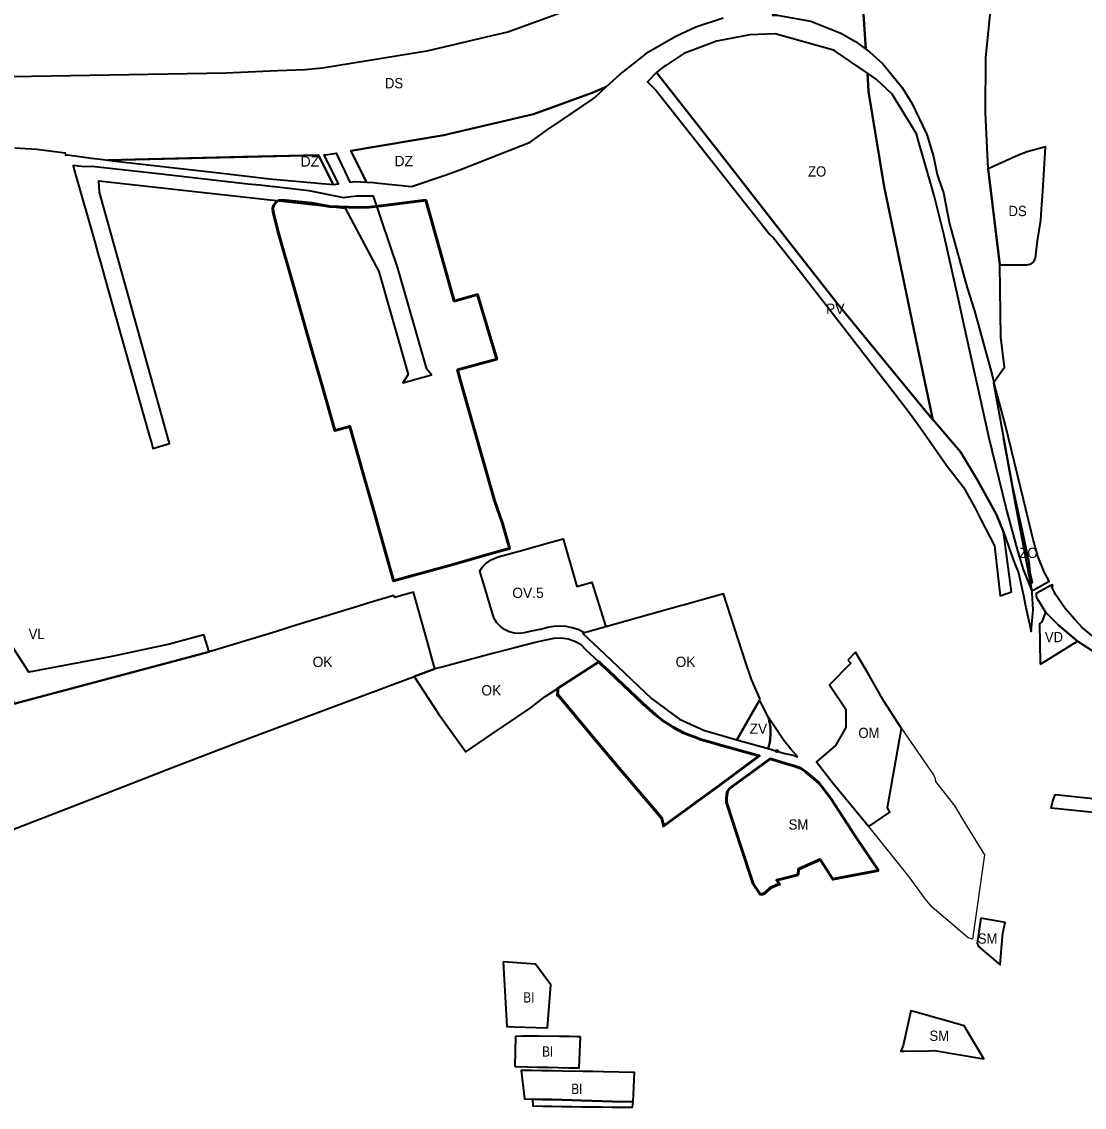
# Model space of a CAD drawing. Extents: x -650276 to -642489, y -1074311 to -1066658.
# Drawn here: x -649019 to -647782, y -1070372 to -1069108 of the extents above; entities that cross this region are included whole.
import ezdxf

# ---------------------------------------------------------------- set-up
doc = ezdxf.new("R2010")
doc.units = 0
doc.header["$LTSCALE"] = 4.8
doc.header["$PDMODE"] = 32
doc.header["$PDSIZE"] = 2.4
for name, color, linetype, lineweight in [('11', 7, 'Continuous', 35), ('12', 7, 'Continuous', 35), ('13', 7, 'Continuous', 35), ('15', 7, 'Continuous', 35), ('18', 7, 'Continuous', 35), ('2', 7, 'Continuous', 35), ('24', 7, 'Continuous', 35), ('25', 7, 'Continuous', 35), ('35', 7, 'Continuous', 35), ('40', 7, 'Continuous', 35), ('42', 7, 'Continuous', 35), ('60', 7, 'Continuous', 53), ('61', 7, 'Continuous', 25)]:
    doc.layers.add(name, color=color, linetype=linetype, lineweight=lineweight)
doc.layers.add('62', color=7, linetype='Continuous')

msp = doc.modelspace()

# ---------------------------------------------------------------- linework, layer by layer
at = {"layer": '11'}
msp.add_lwpolyline([(-648339.05, -1069812.45), (-648363.68, -1069819.31), (-648371.21, -1069815.56), (-648378.1, -1069813.29), (-648385.21, -1069811.91), (-648392.45, -1069811.44), (-648399.68, -1069811.88), (-648406.84, -1069813.23), (-648414.657, -1069815.246), (-648415.99, -1069815.59), (-648430.881, -1069818.663), (-648433.97, -1069819.3), (-648439.89, -1069819.97), (-648445.8, -1069819.51), (-648451.53, -1069817.98), (-648456.88, -1069815.39), (-648461.64, -1069811.86), (-648465.67, -1069807.49), (-648468.82, -1069802.44), (-648470.97, -1069796.9), (-648480.267, -1069765.316), (-648485.44, -1069747.39), (-648485.14, -1069746.55), (-648483.274, -1069743.777), (-648481.79, -1069741.57), (-648477.39, -1069737.44), (-648476.022, -1069736.525), (-648472.4, -1069734.1), (-648464.45, -1069730.89), (-648439.8, -1069724.19), (-648401.288, -1069713.154), (-648388.631, -1069709.738), (-648372.639, -1069765.241), (-648355.015, -1069760.287)], close=True, dxfattribs=at)
at = {"layer": '12'}
msp.add_lwpolyline([(-648057.11, -1069851.12), (-648053.61, -1069854.64), (-648078.54, -1069880.01), (-648059.32, -1069908.27), (-648059.5, -1069929.52), (-648071.58, -1069950.39), (-648093.67, -1069969.42), (-648074.96, -1069993.46), (-648032.85, -1070044.73), (-648008.18, -1070028.25), (-648010.44, -1070023.66), (-648010.94, -1070022.65), (-647994.71, -1069930.53), (-648015.11, -1069898.98), (-648032.94, -1069867.46), (-648048.08, -1069841.95)], close=True, dxfattribs=at)
at = {"layer": '13'}
msp.add_lwpolyline([(-649048.918, -1070055.852), (-648931.057, -1070010.171), (-648849.532, -1069978.559), (-648767.83, -1069946.87), (-648562.242, -1069870.301), (-648537.86, -1069861.22), (-648541.06, -1069849.78), (-648546.97, -1069828.68), (-648562.87, -1069771.85), (-648579.63, -1069776.66), (-648584.65, -1069778.1), (-648586.09, -1069775.75), (-648593.59, -1069778.06), (-648615.88, -1069784.93), (-648627.99, -1069788.67), (-648665.05, -1069799.99), (-648698.31, -1069810.16), (-648722.24, -1069817.54), (-648772.48, -1069832.83), (-648800.85, -1069841.52), (-649028.017, -1069902.109)], dxfattribs=at)
for points in [[(-648159.1, -1069896.39), (-648169.15, -1069873.81), (-648176.78, -1069851.74), (-648201.83, -1069773.86), (-648247.27, -1069786.64), (-648251.94, -1069787.95), (-648339.05, -1069812.45), (-648363.68, -1069819.31), (-648365.81, -1069819.9), (-648340.38, -1069843.78), (-648285.62, -1069895.71), (-648253.13, -1069919.7), (-648223.99, -1069932.96), (-648218.245, -1069934.595), (-648186.268, -1069943.697), (-648160.04, -1069897.73)], [(-648470.79, -1069843.51), (-648528.11, -1069858.73), (-648537.86, -1069861.22), (-648562.242, -1069870.301), (-648533.79, -1069913.49), (-648502.048, -1069957.969), (-648472.6, -1069937.81), (-648426.82, -1069906.88), (-648409.44, -1069893.25), (-648396.87, -1069885.43), (-648395.03, -1069884.22), (-648347.06, -1069853), (-648361.3, -1069839.7), (-648367.64, -1069833.35), (-648374.89, -1069829.22), (-648382.8, -1069826.55), (-648391.08, -1069825.45), (-648399.4, -1069825.97), (-648412.74, -1069828.72), (-648422.75, -1069830.78), (-648422.75, -1069830.78), (-648447.98, -1069837.44)]]:
    msp.add_lwpolyline(points, close=True, dxfattribs=at)
at = {"layer": '15'}
for points in [[(-648147.81, -1069355.26), (-648143.81, -1069359.39), (-648116.93, -1069393.25), (-648052.62, -1069476.32), (-647995.61, -1069549.95), (-647984.36, -1069564.49), (-647980.21, -1069569.97), (-647974.74, -1069577.39), (-647962.93, -1069594.39), (-647942.48, -1069623.82), (-647922.32, -1069649.56), (-647909.25, -1069673.35), (-647902.18, -1069687.23), (-647886.43, -1069718.16), (-647879.96, -1069776.1), (-647866.4, -1069771.43), (-647866.4, -1069771.43), (-647875.82, -1069701.85), (-647883.51, -1069682.71), (-647885.665, -1069678.788), (-647906.16, -1069641.48), (-647925.99, -1069608.57), (-647967.53, -1069559.94), (-648068.71, -1069436.57), (-648127.77, -1069361.38), (-648203.01, -1069264.73), (-648280.1, -1069166.97), (-648290.39, -1069177.69), (-648280.46, -1069187.61), (-648147.81, -1069355.26)], [(-648642.241, -1069324.949), (-648603.386, -1069398.357), (-648569.22, -1069518.4), (-648575.15, -1069528.35), (-648541.88, -1069518.95), (-648547.3, -1069512.136), (-648581.051, -1069394.771), (-648609.304, -1069310.668), (-648629.16, -1069310.91), (-648641.98, -1069312.45), (-648643.83, -1069312.66), (-648684.39, -1069304.67), (-648724.82, -1069299.92), (-648725.82, -1069299.81), (-648741.58, -1069298.16), (-648755.56, -1069296.7), (-648856.68, -1069285.01), (-648937.2, -1069276.37), (-648945.96, -1069276.64), (-648959.11, -1069275.13), (-648957.74, -1069280), (-648934.38, -1069362.79), (-648929.16, -1069381.32), (-648927.37, -1069387.62), (-648927.38, -1069387.623), (-648918.65, -1069418.53), (-648893.86, -1069506.89), (-648870.76, -1069589.26), (-648867.62, -1069599.37), (-648866.17, -1069604.48), (-648847.097, -1069598.995), (-648928.347, -1069306.125), (-648929.112, -1069293.123)], [(-647815.788, -1070007.72), (-647767.622, -1070012.66), (-647714.989, -1069977.087), (-647654.577, -1069936.255), (-647645.274, -1069949.279), (-647755.356, -1070023.682), (-647763.476, -1070029.17), (-647820.515, -1070023.319), (-647818.81, -1070016.41)], [(-648307.13, -1070365.57), (-648319.33, -1070365.32), (-648331.32, -1070364.96), (-648343.31, -1070364.61), (-648355.27, -1070364.25), (-648367.26, -1070363.9), (-648378.49, -1070363.57), (-648389.95, -1070363.23), (-648401.36, -1070362.89), (-648412.88, -1070362.55), (-648424.31, -1070362.21), (-648424.05, -1070370), (-648412.75, -1070370.28), (-648401.35, -1070370.5), (-648390.06, -1070370.72), (-648378.73, -1070370.94), (-648367.67, -1070371.16), (-648355.67, -1070371.28), (-648343.67, -1070371.41), (-648331.67, -1070371.53), (-648319.67, -1070371.65), (-648307.67, -1070371.78)]]:
    msp.add_lwpolyline(points, close=True, dxfattribs=at)
for points in [[(-649032.928, -1069882.782), (-649028.017, -1069902.109), (-648800.85, -1069841.52), (-648806.946, -1069821.79), (-648846.939, -1069832.584), (-648846.94, -1069832.584)], [(-648846.94, -1069832.584), (-648916.03, -1069847.12), (-649010.55, -1069865.09), (-649029.61, -1069835.47)], [(-648149.67, -1069917.83), (-648147, -1069929), (-648147, -1069938), (-648148, -1069947), (-648150, -1069954), (-648139.78, -1069956.93)], [(-648115.23, -1069963.75), (-648123.45, -1069954.79), (-648131.5, -1069944.75), (-648149.67, -1069917.83)], [(-648139.78, -1069956.93), (-648130.36, -1069959.62), (-648120.68, -1069961.63), (-648115.23, -1069963.75)]]:
    msp.add_lwpolyline(points, dxfattribs=at)
msp.add_point((-648139.78, -1069956.93), dxfattribs=at)
at = {"layer": '18'}
for points in [[(-648182.01, -1070067.11), (-648197.23, -1070020.37), (-648198.22, -1070016.4), (-648198.48, -1070012.3), (-648198.17, -1070008.05), (-648197.19, -1070003.94), (-648194.84, -1070000.49), (-648147.46, -1069966.19)], [(-648147.46, -1069966.19), (-648140.96, -1069968.01), (-648128.48, -1069971.7)], [(-648128.48, -1069971.7), (-648118.75, -1069974.53), (-648111.44, -1069977.32)], [(-648111.44, -1069977.32), (-648105.79, -1069981.56), (-648091.06, -1069994.07), (-648077.68, -1070011.06), (-648046.83, -1070058.62), (-648021.35, -1070096.14), (-648074.76, -1070106.17)], [(-648152.35, -1070121.05), (-648153.85, -1070122.38), (-648156.07, -1070123.54), (-648159.02, -1070123.71), (-648159.89, -1070122.49), (-648167.48, -1070111.75), (-648182.01, -1070067.11)], [(-648074.76, -1070106.17), (-648089.22, -1070083.27), (-648114.7, -1070094.68), (-648115.11, -1070101.26), (-648139.91, -1070107.48), (-648136.61, -1070111.97)], [(-648136.61, -1070111.97), (-648139.45, -1070112.79), (-648147.02, -1070116.35), (-648152.35, -1070121.05)]]:
    msp.add_lwpolyline(points, dxfattribs=at)
for points in [[(-647902.17, -1070151.64), (-647906.6, -1070180.65), (-647905.17, -1070184.5), (-647879.81, -1070206.08), (-647878.18, -1070186.33), (-647876.74, -1070168.88), (-647873.97, -1070156.58)], [(-647962.82, -1070305.9), (-647956.36, -1070305.77), (-647898.82, -1070315.51), (-647921.51, -1070276.76), (-647979.24, -1070260.71), (-647983.6, -1070259.5), (-647992.71, -1070300.01), (-647995.46, -1070306.55), (-647991.12, -1070306.46)]]:
    msp.add_lwpolyline(points, close=True, dxfattribs=at)
at = {"layer": '2'}
msp.add_lwpolyline([(-648458.28, -1070202.26), (-648454.038, -1070277.767), (-648446.18, -1070278.15), (-648406.8, -1070279.32), (-648403.04, -1070229.15), (-648420.7, -1070204.96)], close=True, dxfattribs=at)
for points in [[(-648368.25, -1070289.71), (-648372.1, -1070289.59), (-648380.97, -1070289.44), (-648392.94, -1070289.25), (-648416.93, -1070288.85), (-648420.39, -1070288.79), (-648428.98, -1070288.92), (-648435.93, -1070288.95), (-648444.15, -1070289.16), (-648444.85, -1070324.47)], [(-648444.85, -1070324.47), (-648444.85, -1070324.47), (-648430.02, -1070324.76), (-648418.1, -1070325), (-648406.09, -1070325.23), (-648394.08, -1070325.47), (-648382.06, -1070325.7), (-648370.07, -1070325.94), (-648368.25, -1070289.71)], [(-648307.13, -1070365.57), (-648305.47, -1070331.23), (-648341.46, -1070330.48), (-648353.32, -1070330.23), (-648365.35, -1070329.98), (-648389.43, -1070329.58), (-648401.41, -1070329.39), (-648413.45, -1070329.19), (-648425.43, -1070329), (-648437.65, -1070328.8), (-648433.46, -1070361.94), (-648424.31, -1070362.21), (-648412.88, -1070362.55)], [(-648412.88, -1070362.55), (-648401.36, -1070362.89), (-648389.95, -1070363.23), (-648378.49, -1070363.57), (-648367.26, -1070363.9), (-648355.27, -1070364.25), (-648343.31, -1070364.61), (-648331.32, -1070364.96), (-648319.33, -1070365.32)]]:
    msp.add_lwpolyline(points, dxfattribs=at)
at = {"layer": '24'}
for points in [[(-648392.002, -1069097.554), (-648451.865, -1069119.456), (-648547.243, -1069141.81), (-648668.959, -1069161.838), (-648688.912, -1069163.603), (-648721.315, -1069164.952), (-648781.015, -1069167.44), (-649076.02, -1069172.683)], [(-649026.955, -1069254.366), (-649001.3, -1069255.92), (-648968.49, -1069260.36), (-648968.05, -1069263.06), (-648965.8, -1069262.75), (-648937.91, -1069266.51), (-648924.13, -1069268.21), (-648918.889, -1069268.875), (-648673.267, -1069262.895), (-648656.242, -1069297.116), (-648650.06, -1069296.39), (-648650.58, -1069295.34), (-648658.18, -1069280.27), (-648666.827, -1069262.738), (-648665.007, -1069262.694), (-648665.007, -1069262.694), (-648652.716, -1069260.657), (-648642.74, -1069281.93), (-648636.85, -1069294.49), (-648630.82, -1069293.63), (-648617.434, -1069294.508), (-648635.818, -1069257.857), (-648527.693, -1069239.938), (-648423.173, -1069215.44), (-648354.978, -1069190.492), (-648338.523, -1069183.389), (-648322.14, -1069168.56), (-648306.83, -1069156.57), (-648289.25, -1069142.79), (-648257.5, -1069124.41), (-648234.22, -1069113.6), (-648202.46, -1069103.3)]]:
    msp.add_lwpolyline(points, dxfattribs=at)
msp.add_lwpolyline([(-647860.52, -1069390.72), (-647848.24, -1069390.65), (-647845.25, -1069390.07), (-647843.41, -1069389.23), (-647841.81, -1069387.99), (-647840.42, -1069386.51), (-647839.4, -1069384.73), (-647838.79, -1069382.86), (-647836.2, -1069362.68), (-647832.29, -1069338.58), (-647832.29, -1069338.58), (-647831.19, -1069320.69), (-647830.23, -1069305.38), (-647826.928, -1069253.199), (-647848.17, -1069259.21), (-647858.37, -1069263.03), (-647893.553, -1069279.017), (-647880.326, -1069390.832)], close=True, dxfattribs=at)
at = {"layer": '25'}
msp.add_line((-647862.266, -1069668.613), (-647843.449, -1069768.252), dxfattribs=at)
for points in [[(-647948.18, -1069057.276), (-648039.666, -1069069.279), (-648040.705, -1069069.548), (-648036.291, -1069139.458)], [(-647893.553, -1069279.017), (-647896.67, -1069213.573), (-647896.362, -1069149.171), (-647886.615, -1069053.052)], [(-648036.291, -1069139.458), (-648031.92, -1069142.67), (-648016.36, -1069156.54), (-647993.8, -1069184.11)], [(-648005.47, -1069192.09), (-648024.02, -1069174.7), (-648034.421, -1069167.61)], [(-648034.421, -1069167.61), (-648034.421, -1069167.61), (-648033, -1069189), (-648015, -1069300), (-648010.092, -1069322.087), (-647980.331, -1069465.915), (-647958.34, -1069570.699), (-647925.99, -1069608.57), (-647906.16, -1069641.48), (-647885.665, -1069678.788), (-647885.663, -1069678.794), (-647883.51, -1069682.71), (-647875.82, -1069701.85), (-647875.82, -1069701.85), (-647864.19, -1069735.12), (-647858.44, -1069749.43), (-647852.63, -1069775.7), (-647850.66, -1069785.74), (-647849.165, -1069793.367)], [(-648354.978, -1069190.492), (-648423.173, -1069215.44), (-648527.693, -1069239.938), (-648635.818, -1069257.857)], [(-648526.15, -1069286.21), (-648508.95, -1069280.01), (-648427.08, -1069247.75), (-648407.73, -1069233.88), (-648389.91, -1069221.86), (-648355.81, -1069198.88), (-648351.77, -1069195.88), (-648338.523, -1069183.389), (-648354.978, -1069190.492)], [(-647993.8, -1069184.11), (-647982.58, -1069202.33), (-647965.06, -1069238.95), (-647957.56, -1069264.74), (-647953.01, -1069285.73), (-647951.841, -1069289.09)], [(-647962.2, -1069290.88), (-647974.81, -1069246.86), (-647977.29, -1069238.21), (-648005.47, -1069192.09)], [(-648635.818, -1069257.857), (-648622.995, -1069283.455), (-648617.434, -1069294.508)], [(-647880.326, -1069390.832), (-647880.326, -1069390.832), (-647893.553, -1069279.017)], [(-648617.434, -1069294.508), (-648609.425, -1069295.033), (-648603.228, -1069295.53), (-648565.18, -1069299.46), (-648526.15, -1069286.21)], [(-647852.78, -1069745.71), (-647859.722, -1069722.428), (-647872.87, -1069673.56), (-647892.79, -1069591.06), (-647892.789, -1069591.06), (-647893.75, -1069587.08), (-647922.04, -1069459.71), (-647925.16, -1069445.68), (-647928.41, -1069431.03), (-647945.28, -1069355.1), (-647956.27, -1069311.58), (-647962.2, -1069290.88)], [(-647951.841, -1069289.09), (-647945.63, -1069306.95), (-647938.77, -1069343.17), (-647918.08, -1069417.43), (-647909.67, -1069444.46), (-647889.22, -1069519.32), (-647887.087, -1069527.229), (-647885.782, -1069525.389), (-647882.551, -1069520.835), (-647878.73, -1069515.45)], [(-647878.73, -1069515.45), (-647874.75, -1069509.84), (-647878.93, -1069475.09), (-647880.318, -1069391.297), (-647880.326, -1069390.832)], [(-647843.449, -1069768.252), (-647844.371, -1069761.991), (-647842.438, -1069760.647), (-647845.086, -1069748.753), (-647846.484, -1069736.663), (-647855.158, -1069695.232), (-647865.69, -1069647.32), (-647876.061, -1069592.206), (-647862.266, -1069668.613)], [(-647841.402, -1069792.351), (-647842.489, -1069773.282), (-647842.622, -1069770.956), (-647843.337, -1069769.013), (-647843.443, -1069768.293), (-647852.78, -1069745.71)], [(-647849.165, -1069793.367), (-647843.74, -1069817.63), (-647841.402, -1069792.351)]]:
    msp.add_lwpolyline(points, dxfattribs=at)
msp.add_lwpolyline([(-648730.66, -1069290.43), (-648656.242, -1069297.116), (-648673.267, -1069262.895), (-648761.189, -1069265.035), (-648918.889, -1069268.875), (-648909.86, -1069270.02), (-648861.49, -1069275.34), (-648785.92, -1069284.2), (-648730.66, -1069290.43)], close=True, dxfattribs=at)
msp.add_arc((-648354.978, -1069190.492), 0.000000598, 264.13978, 298.69712, dxfattribs=at)
at = {"layer": '35'}
msp.add_lwpolyline([(-647833.172, -1069855.944), (-647833.172, -1069855.944), (-647831.62, -1069854.99), (-647789.55, -1069829.12), (-647811.83, -1069810.39), (-647827.16, -1069795.32), (-647831.32, -1069806.56), (-647833.91, -1069808.91), (-647833.2, -1069854.15)], close=True, dxfattribs=at)
at = {"layer": '40'}
msp.add_lwpolyline([(-648150, -1069954), (-648148, -1069947), (-648147, -1069938), (-648147, -1069929), (-648149.67, -1069917.83), (-648157.81, -1069902.06), (-648160.04, -1069897.73), (-648186.268, -1069943.697)], close=True, dxfattribs=at)
at = {"layer": '42'}
for points in [[(-648100.37, -1069107.1), (-648065.16, -1069121.12), (-648048.06, -1069130.81), (-648036.291, -1069139.458), (-648040.705, -1069069.547), (-648124.327, -1069091.181), (-648144.867, -1069099.987), (-648139.27, -1069100.05), (-648100.37, -1069107.1)], [(-648015, -1069300), (-648033, -1069189), (-648034.421, -1069167.61), (-648071.9, -1069142.06), (-648073.66, -1069140.86), (-648141.92, -1069121.66), (-648171.14, -1069122.83), (-648207.77, -1069129.95), (-648209.89, -1069130.36), (-648226.51, -1069136.57), (-648248.14, -1069144.65), (-648268.87, -1069158.61), (-648270.92, -1069159.99), (-648275.19, -1069162.87), (-648280.1, -1069166.97), (-648203.01, -1069264.73), (-648127.77, -1069361.38), (-648068.71, -1069436.57), (-647967.53, -1069559.94), (-647958.214, -1069571.3), (-647980.331, -1069465.915), (-648010.092, -1069322.087)], [(-647828.61, -1069748.41), (-647835.76, -1069730.01), (-647841.26, -1069710.69), (-647852.44, -1069664.03), (-647873.43, -1069577.87), (-647887.087, -1069527.229), (-647887.649, -1069528.021), (-647865.69, -1069647.32), (-647855.158, -1069695.232), (-647846.484, -1069736.663), (-647845.086, -1069748.753), (-647842.438, -1069760.647), (-647844.371, -1069761.991), (-647843.337, -1069769.013), (-647842.798, -1069770.477), (-647840.49, -1069769.3), (-647822.54, -1069759.29)]]:
    msp.add_lwpolyline(points, close=True, dxfattribs=at)
msp.add_lwpolyline([(-647760.79, -1069832.61), (-647783.96, -1069813.49), (-647792.84, -1069803.65), (-647804.02, -1069791.01), (-647815.36, -1069774.66), (-647819.78, -1069765.84), (-647818.28, -1069764.99), (-647818.73, -1069763.53), (-647820.09, -1069763.65), (-647838, -1069773.63), (-647837.93, -1069777.45), (-647827.16, -1069795.32), (-647811.83, -1069810.39), (-647789.55, -1069829.12), (-647761.54, -1069847.24)], dxfattribs=at)
at = {"layer": '60'}
for points in [[(-648726.23, -1069329), (-648720.26, -1069352.66), (-648699.95, -1069424.34), (-648683.77, -1069480.8), (-648668.96, -1069532.87), (-648654.264, -1069583.761), (-648636.98, -1069578.86), (-648620.94, -1069635.45), (-648607.53, -1069682.78), (-648585.959, -1069758.915), (-648518.24, -1069739.91), (-648464.32, -1069724.64), (-648450.939, -1069720.921), (-648452.25, -1069716.34), (-648459.27, -1069691.81), (-648468.49, -1069665.23), (-648508.35, -1069524.48), (-648511.542, -1069513.207), (-648465.94, -1069500.68), (-648488.2, -1069425.34), (-648515.4, -1069433.05), (-648548.56, -1069315.61), (-648600.64, -1069321.87), (-648614.51, -1069323.62), (-648627.48, -1069324.05), (-648660.81, -1069322.69), (-648681.2, -1069318.86), (-648715.26, -1069315.58), (-648720.16, -1069316.01), (-648723.27, -1069318.05), (-648725.43, -1069321.26), (-648726.48, -1069324.93)], [(-648205.77, -1069996.14), (-648160.27, -1069962.63), (-648208.27, -1069949.26), (-648214.42, -1069947.46), (-648227.23, -1069943.8), (-648236.06, -1069940.52), (-648242.53, -1069937.92), (-648248.62, -1069935.54), (-648254.18, -1069932.68), (-648260.08, -1069929.44), (-648265.24, -1069926.2), (-648271.62, -1069922.1), (-648281.22, -1069914.79), (-648295.88, -1069901.64), (-648318.63, -1069879.94), (-648321, -1069877.7), (-648323.3, -1069875.52), (-648325.6, -1069873.34), (-648327.82, -1069871.23), (-648330.09, -1069869.08), (-648332.31, -1069866.98), (-648334.54, -1069864.87), (-648336.73, -1069862.79), (-648339.13, -1069860.51), (-648343.37, -1069856.49), (-648347.06, -1069853), (-648395.03, -1069884.22), (-648394.65, -1069886.59), (-648395.15, -1069892.61), (-648394.35, -1069891.95), (-648350.48, -1069944.78), (-648323.69, -1069976.45), (-648316.73, -1069984.68), (-648278.69, -1070029.47), (-648273.67, -1070035.38), (-648271.65, -1070043.3), (-648271.95, -1070044.31), (-648271.5, -1070043.98), (-648235.74, -1070018.05), (-648234.79, -1070017.36), (-648227.16, -1070011.83)]]:
    msp.add_lwpolyline(points, close=True, dxfattribs=at)
for points in [[(-648128.48, -1069971.7), (-648140.96, -1069968.01), (-648147.46, -1069966.19), (-648194.84, -1070000.49)], [(-648111.44, -1069977.32), (-648118.75, -1069974.53), (-648128.48, -1069971.7)], [(-648021.35, -1070096.14), (-648046.83, -1070058.62), (-648077.68, -1070011.06), (-648091.06, -1069994.07), (-648105.79, -1069981.56), (-648111.44, -1069977.32)], [(-648194.84, -1070000.49), (-648197.19, -1070003.94), (-648198.17, -1070008.05), (-648198.48, -1070012.3), (-648198.22, -1070016.4), (-648197.23, -1070020.37), (-648182.01, -1070067.11)], [(-648182.01, -1070067.11), (-648167.48, -1070111.75), (-648159.89, -1070122.49), (-648159.02, -1070123.71), (-648156.07, -1070123.54)], [(-648115.11, -1070101.26), (-648114.7, -1070094.68), (-648089.22, -1070083.27), (-648074.76, -1070106.17), (-648021.35, -1070096.14)], [(-648152.35, -1070121.05), (-648147.02, -1070116.35), (-648139.45, -1070112.79), (-648136.61, -1070111.97), (-648139.91, -1070107.48), (-648115.11, -1070101.26)], [(-648156.07, -1070123.54), (-648153.85, -1070122.38), (-648152.35, -1070121.05)]]:
    msp.add_lwpolyline(points, dxfattribs=at)
at = {"layer": '61'}
msp.add_lwpolyline([(-648008.18, -1070028.25), (-648010.94, -1070022.65), (-647994.71, -1069930.53), (-647957.24, -1069984.73), (-647955.65, -1069988.28), (-647955.08, -1069992.58), (-647932.43, -1070021.22), (-647923.61, -1070036.27), (-647898.15, -1070077.99), (-647911.88, -1070175.85), (-647917.1, -1070174.56), (-647959.1, -1070138.59), (-647967.22, -1070129.11), (-647976.36, -1070116.1), (-647985.64, -1070103.59), (-648032.85, -1070044.73)], close=True, dxfattribs=at)

# ---------------------------------------------------------------- texts
at = {"layer": '62'}
for s, width, p in [('DS', 0.95, (-648596.118, -1069185.225)), ('ZO', 0.95, (-648103.473, -1069288.058)), ('DS', 0.95, (-647870.044, -1069334.044)), ('ZO', 0.95, (-647857.423, -1069732.188)), ('VL', 0.95, (-649010.928, -1069826.6)), ('VD', 0.95, (-647827.767, -1069830.204)), ('OM', 0.95, (-648044.853, -1069941.852)), ('SM', 0.95, (-648126.077, -1070048.464)), ('SM', 0.95, (-647905.887, -1070181.298)), ('BI', 0.85, (-648435.024, -1070249.825)), ('SM', 0.95, (-647962.077, -1070294.464)), ('BI', 0.85, (-648413.024, -1070312.825)), ('BI', 0.85, (-648379.14, -1070356.31))]:
    msp.add_text(s, height=12, dxfattribs=dict(at, width=width)).set_placement(p)
for s, p in [('DZ', (-648694.171, -1069276.367)), ('DZ', (-648584.843, -1069275.949)), ('PV', (-648082.5, -1069447.958)), ('OV.5', (-648447.819, -1069778.742)), ('OK', (-648680.267, -1069859.087)), ('OK', (-648257.724, -1069859.087)), ('OK', (-648483.81, -1069892.185)), ('ZV', (-648171.5, -1069936.875))]:
    msp.add_text(s, height=12, dxfattribs=at).set_placement(p)

doc.saveas('drawing.dxf')
